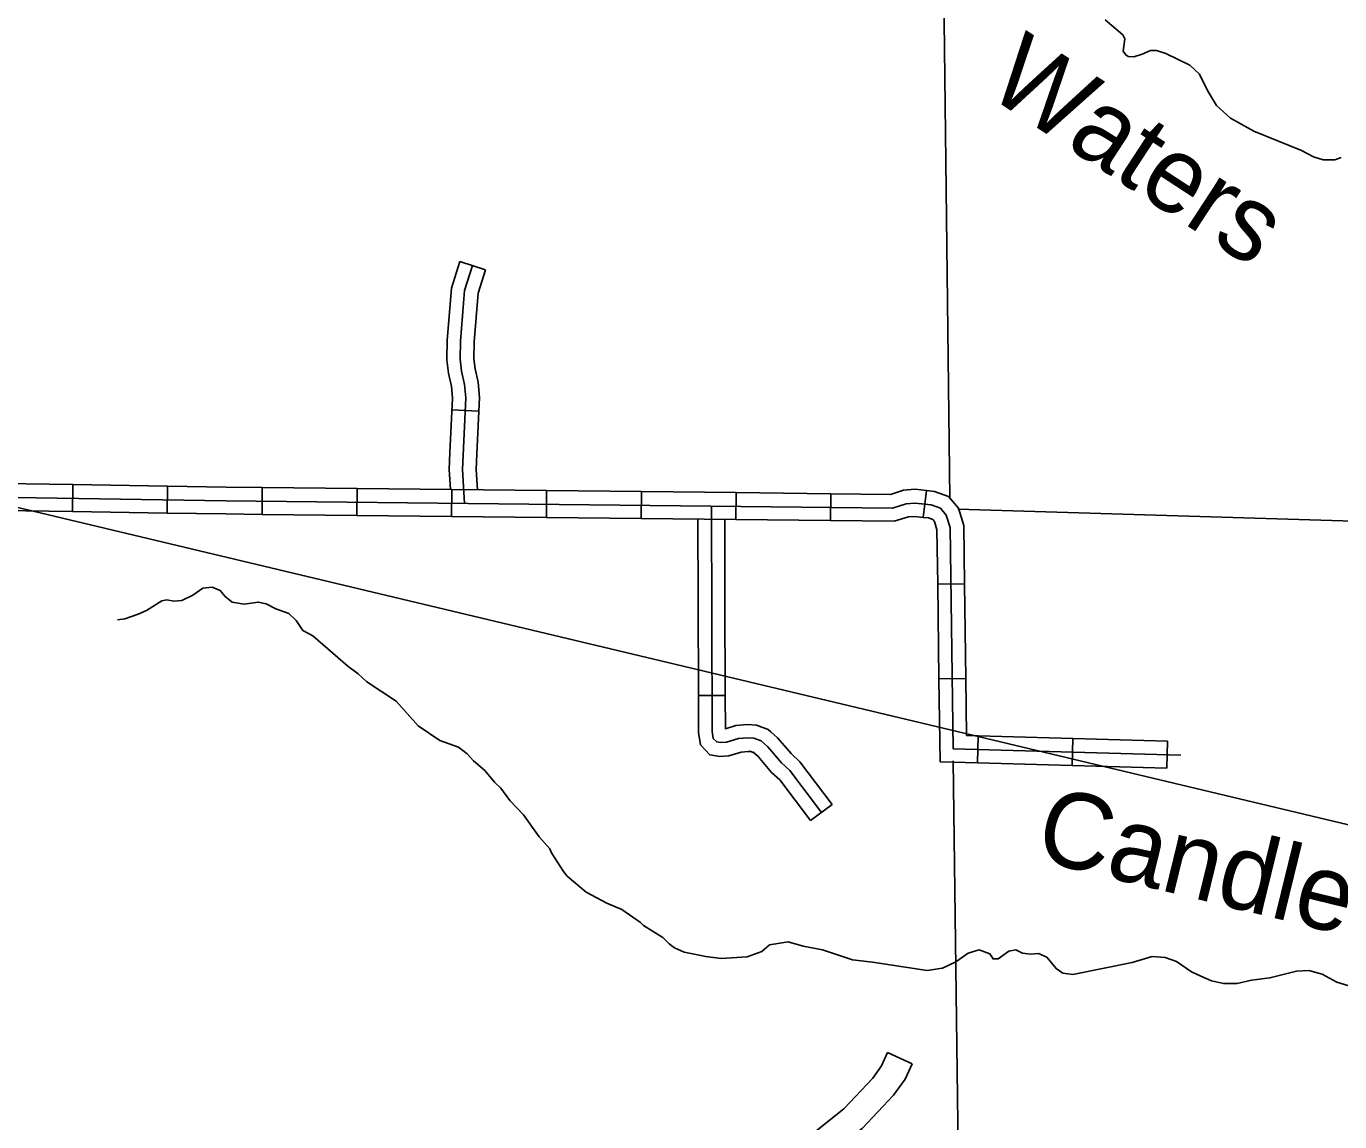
# Model space of a CAD drawing. Extents: x 1212896 to 1368412, y 378476 to 478763.
# Drawn here: x 1299837 to 1307154, y 397540 to 403644 of the extents above; entities that cross this region are included whole.
import ezdxf

# ---------------------------------------------------------------- set-up
doc = ezdxf.new("R2010")
doc.units = 0
for name, color, linetype in [('Level 32', 7, 'Continuous'), ('Level 35', 7, 'Continuous'), ('Level 45', 7, 'Continuous'), ('Level 5', 7, 'Continuous'), ('R_Draft', 7, 'Continuous')]:
    doc.layers.add(name, color=color, linetype=linetype)

msp = doc.modelspace()

# ---------------------------------------------------------------- linework, layer by layer
at = {"layer": 'Level 32'}
for p, q in [((1300093.9, 400940.5), (1300096.3, 401090.5)), ((1300621.8, 400932.1), (1300624.2, 401082.1)), ((1301150.1, 400924.7), (1301151.7, 401074.7)), ((1301678.1, 400918.9), (1301679.7, 401068.9)), ((1302206, 400913.1), (1302207.7, 401063.1)), ((1302734, 400907.3), (1302735.7, 401057.3)), ((1303262, 400901.5), (1303263.6, 401051.5)), ((1303789.9, 400895.7), (1303791.6, 401045.7)), ((1304317.9, 400889.9), (1304319.6, 401039.9)), ((1304834.1, 400908.2), (1304851.4, 401057.2)), ((1304914.3, 400536), (1305064.3, 400538)), ((1304921.3, 400008), (1305071.3, 400010)), ((1305135.3, 399540.9), (1305139.5, 399690.9)), ((1305663.1, 399526.2), (1305667.3, 399676.1)), ((1306190.9, 399511.4), (1306195.1, 399661.3))]:
    msp.add_line(p, q, dxfattribs=at)
for points in [[(1299568.3, 401098.9), (1300096.3, 401090.5)], [(1300096.3, 401090.5), (1300624.2, 401082.1)], [(1300624.2, 401082.1), (1300949.6, 401076.9), (1301151.7, 401074.7)], [(1295871.3, 401056), (1299185.8, 401028.6), (1300948.5, 401000.5), (1304661.7, 400959.8), (1304738.2, 400983.5), (1304787.7, 400987.6), (1304878.8, 400977.1), (1304929.8, 400959.2), (1304962.4, 400921), (1304983.8, 400851)], [(1301151.7, 401074.7), (1301679.7, 401068.9)], [(1301679.7, 401068.9), (1302207.7, 401063.1)], [(1302207.7, 401063.1), (1302735.7, 401057.3)], [(1302735.7, 401057.3), (1303263.6, 401051.5)], [(1303263.6, 401051.5), (1303791.6, 401045.7)], [(1303791.6, 401045.7), (1304319.6, 401039.9)], [(1304319.6, 401039.9), (1304650.5, 401036.3), (1304723.5, 401058.9), (1304789, 401064.4), (1304851.4, 401057.2)], [(1304851.4, 401057.2), (1304896, 401052), (1304974.5, 401024.5), (1305030.8, 400958.5), (1305060, 400863), (1305064.3, 400538)], [(1299565.9, 400948.9), (1300093.9, 400940.5)], [(1300093.9, 400940.5), (1300621.8, 400932.1)], [(1300621.8, 400932.1), (1300947.6, 400926.9), (1301150.1, 400924.7)], [(1301150.1, 400924.7), (1301678.1, 400918.9)], [(1301678.1, 400918.9), (1302206, 400913.1)], [(1302206, 400913.1), (1302734, 400907.3)], [(1302734, 400907.3), (1303262, 400901.5)], [(1303262, 400901.5), (1303789.9, 400895.7)], [(1303789.9, 400895.7), (1304317.9, 400889.9)], [(1304317.9, 400889.9), (1304672.4, 400886), (1304752.3, 400910.8), (1304786.5, 400913.7), (1304834.1, 400908.2)], [(1304834.1, 400908.2), (1304862.2, 400904.9), (1304886.7, 400896.3), (1304896.5, 400884.8), (1304910.3, 400839.5), (1304914.3, 400536)], [(1304983.8, 400851), (1305000.1, 399618.4), (1306269.7, 399582.8)], [(1304914.3, 400536), (1304921.3, 400008)], [(1305064.3, 400538), (1305071.3, 400010)], [(1304921.3, 400008), (1304927.5, 399546.7), (1305135.3, 399540.9)], [(1305071.3, 400010), (1305075.5, 399692.7), (1305139.5, 399690.9)], [(1305139.5, 399690.9), (1305667.3, 399676.1)], [(1305667.3, 399676.1), (1306195.1, 399661.3)], [(1305135.3, 399540.9), (1305663.1, 399526.2)], [(1305663.1, 399526.2), (1306190.9, 399511.4)]]:
    msp.add_lwpolyline(points, dxfattribs=at)
at = {"layer": 'Level 35'}
for points in [[(1305847.5, 403679.5), (1305945.1, 403596.4), (1305956.3, 403574.5), (1305948.1, 403506.2), (1305962.2, 403484.4), (1305975, 403476.2), (1306006.2, 403474.8), (1306053, 403488.3), (1306099.6, 403508.9), (1306132.6, 403509.2), (1306184.6, 403492.8), (1306319.9, 403428.1), (1306373.3, 403377.6), (1306417.1, 403286.8), (1306467.8, 403202.2), (1306545.4, 403131.9), (1306674.8, 403059.2), (1306941.2, 402951.8), (1307008.4, 402917.5), (1307062.4, 402900), (1307127.3, 402900.7), (1307163, 402913.1)], [(1300344.5, 400336.5), (1300385.2, 400342.4), (1300459.5, 400368.1), (1300507, 400389.2), (1300591.6, 400442.1), (1300620.6, 400447.9), (1300659.5, 400441.6), (1300703.5, 400444), (1300763.6, 400473.9), (1300819.6, 400514.3), (1300872.3, 400519.2), (1300917.7, 400500.4), (1300944.3, 400466.9), (1300984, 400434.7), (1301050, 400425.1), (1301129.4, 400436.3), (1301173.8, 400425.8), (1301226.3, 400397.9), (1301299.7, 400371.9), (1301339.5, 400333.2), (1301376.6, 400277.8), (1301432.9, 400248.7), (1301627.4, 400079.8), (1301686.2, 400037), (1301733.2, 399990.9), (1301898.2, 399884.3), (1302019.9, 399746.6), (1302140.5, 399664), (1302245.1, 399627.2), (1302293.5, 399591.3), (1302328.6, 399550.9), (1302391.7, 399496.9), (1302444.9, 399433.1), (1302480.6, 399398.8), (1302530, 399330.8), (1302607.6, 399250.3), (1302693.6, 399128.1), (1302753.4, 399062), (1302762.9, 399038.1), (1302829.1, 398934.3), (1302850.6, 398908.7), (1302955.4, 398818.8), (1303071.5, 398758.2), (1303154.1, 398722.9), (1303258.4, 398651), (1303274.8, 398634.3), (1303383, 398567.5), (1303417.7, 398531.2), (1303447.2, 398508.8), (1303502.6, 398485), (1303621.9, 398460.5), (1303708.9, 398450.4), (1303853.4, 398459.5), (1303934.6, 398488.4), (1303976.7, 398525.4), (1304082.2, 398542.9), (1304164.4, 398519.5), (1304272.7, 398498.8), (1304440.5, 398442.3), (1304551.6, 398429.7), (1304855, 398383.2), (1304941.5, 398396.1), (1305015.6, 398430.8), (1305083.4, 398479.4), (1305144.8, 398498.8), (1305204.2, 398476), (1305222.8, 398447.4), (1305250.7, 398447.9), (1305310.7, 398490.4), (1305350, 398498.2), (1305387.7, 398480), (1305430.8, 398475), (1305476.6, 398477), (1305521.9, 398457.9), (1305574.2, 398393.9), (1305610.7, 398368.6)], [(1305610.7, 398368.6), (1305666.8, 398361.8), (1305998.6, 398427.2), (1306109.5, 398460.6), (1306181.6, 398456.3), (1306244, 398433.6), (1306329.1, 398376.3), (1306380.5, 398351.4), (1306438.9, 398325.6), (1306506.1, 398311), (1306582, 398310.7), (1306663.4, 398328.5), (1306764.9, 398341.7), (1306913.8, 398379), (1306981.5, 398383.5), (1307055.8, 398362.1), (1307138.6, 398318.8), (1307247.1, 398285.1)]]:
    msp.add_lwpolyline(points, dxfattribs=at)
at = {"layer": 'Level 45'}
for p, q in [((1302252.4, 402333.2), (1302395.4, 402287.7)), ((1302207.1, 401507.6), (1302356.9, 401500.5)), ((1303730.8, 399915), (1303580.8, 399914.6)), ((1304326.1, 399308.5), (1304206.3, 399219.1)), ((1304634.7, 397925.6), (1304771.4, 397863.8))]:
    msp.add_line(p, q, dxfattribs=at)
for points in [[(1302252.4, 402333.2), (1302205.6, 402185.9), (1302181.5, 401892.7), (1302180.5, 401791.5)], [(1302322.6, 402310.9), (1302278.3, 402171.6), (1302255.1, 401889.3), (1302254.1, 401790.1), (1302261.1, 401723.4), (1302278.5, 401649.1), (1302285.2, 401574), (1302266.4, 401175), (1302278.2, 400985.9)], [(1302395.4, 402287.7), (1302353.7, 402156.7), (1302331.4, 401885.8), (1302330.5, 401790)], [(1302180.5, 401791.5), (1302180.5, 401786.6), (1302188.4, 401711.2), (1302205.6, 401637.4), (1302211.5, 401572.5), (1302197.1, 401269.2)], [(1302330.5, 401793.8), (1302336.6, 401736.2), (1302354.1, 401661.3), (1302361.8, 401575.6), (1302347, 401262.2)], [(1302197.1, 401269.2), (1302192.7, 401174.5), (1302199.6, 401063.2)], [(1302347, 401262.2), (1302342.9, 401175.6), (1302350, 401061.5)], [(1303653.9, 400970.8), (1303657.7, 399715.7), (1303664, 399676.3), (1303683, 399656.7), (1303705, 399652.9), (1303737.4, 399654.8), (1303804.8, 399675.3), (1303856.5, 399680.5), (1303889.5, 399678.2), (1303930.8, 399662.6), (1303968.4, 399628.8), (1304044.2, 399540.2), (1304091.1, 399497.2), (1304266.8, 399264.4)], [(1303577.8, 400898), (1303579.2, 400442.6)], [(1303727.8, 400896.4), (1303729.2, 400443)], [(1303579.2, 400442.6), (1303580.8, 399914.6)], [(1303729.2, 400443), (1303730.8, 399915)], [(1303580.8, 399914.6), (1303581.4, 399709.5), (1303592.4, 399640.5), (1303645.4, 399585.7), (1303700.7, 399576.1), (1303750.9, 399579.1), (1303819.8, 399600.1), (1303857.7, 399603.8), (1303873, 399602.8), (1303890.4, 399596.2)], [(1303730.8, 399915), (1303731.3, 399729.9), (1303790.3, 399747.9), (1303855.4, 399754.4), (1303905.4, 399750.9), (1303969.7, 399726.6), (1303985.4, 399712.5)], [(1303985.4, 399712.5), (1304021.2, 399680.4), (1304097.3, 399591.5), (1304145.8, 399546.8), (1304325.6, 399308.8)], [(1303885.2, 399600.9), (1303913.7, 399575.3), (1303989.2, 399487.1), (1304034.3, 399445.6), (1304205.9, 399218.4)], [(1304634.7, 397925.6), (1304601.6, 397852.4), (1304552.6, 397784), (1304392, 397612.6), (1304319.3, 397554.8)], [(1304771.4, 397863.8), (1304732.2, 397777.1), (1304668.8, 397688.7), (1304494, 397502), (1304412.6, 397437.3)], [(1304319.3, 397554.8), (1304149.3, 397419.7), (1303927.3, 397267.4), (1303766.8, 397095)]]:
    msp.add_lwpolyline(points, dxfattribs=at)
at = {"layer": 'Level 5'}
for points in [[(1304920.3, 406180.6), (1304982, 401013.3)], [(1305026.3, 400954.4), (1310417.6, 400790.7)], [(1305000.9, 399551.8), (1305051.5, 395660.5), (1305066.5, 393095.4)]]:
    msp.add_lwpolyline(points, dxfattribs=at)
at = {"layer": 'R_Draft'}
msp.add_line((1324691.3, 395024.3), (1283954.6, 404739.3), dxfattribs=at)

# ---------------------------------------------------------------- texts
at = {"layer": 'Level 35'}
for s, height, rotation, p in [('Waters', 422.4, 326.8432, (1305171.6, 403272.1)), ('Candlestick', 422.399, 346.24642, (1305442.9, 399005))]:
    msp.add_text(s, height=height, rotation=rotation, dxfattribs=at).set_placement(p)

doc.saveas('drawing.dxf')
